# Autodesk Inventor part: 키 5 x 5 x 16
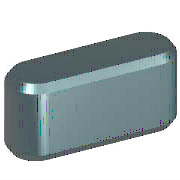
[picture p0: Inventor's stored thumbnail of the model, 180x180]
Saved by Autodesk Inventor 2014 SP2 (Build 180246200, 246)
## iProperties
IsCustomPart: 1
Created: 2012-02
Part Number: 키 5 x 5 x 16
Material: 강철, 연강
Description: 키 및 해당 키홈
Document SubType Name: Modeling
Standard: KS B 1311
Designer: mduedu
Standards Organization: KS
Language: ko-KR
Size Designation: 5 x 5 x 16
Categories: <MemberInstance><Categories><Category DisplayName="샤프트 부품" InternalName="7f7aeb1f-a693-4053-b835-cee3144e0d98" Mnemonic="SHFT"><Category DisplayName="키" Interna
Density: 1 g/cm^3
Appearance: 강철
Author: mduedu
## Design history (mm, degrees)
workplane "Work Plane1"
workplane "Work Plane2"
sketch "스케치1"
  geometry: L1 (2.5, 2.5)-(13.5, 2.5); L2 (13.5, -2.5)-(2.5, -2.5); L3 (0, 9.4)-(0, -7.4) reference; L4 (-5, 0)-(30, 0) reference; L5 (16, 0)-(16, 7); A1 r 2.5 centre (2.5, 0) between (2.5, 2.5) and (2.5, -2.5); A2 r 2.5 centre (13.5, 0) between (13.5, -2.5) and (13.5, 2.5)
  constraints: 6 end point, 5 point on circle, 4 tangent, 3 point on line, 2 centre point, 1 horizontal, 1 parallel, 1 perpendicular
  dimensions: "d0" = 2.5 radius of A1 (= 0.5 x PB); "d13" = 2.5 radius of A2 (= 0.5 x PB); "d14" = 16 distance between parallel lines of L5 L3 (= NLG)
extrude "본체1" new body sketch "스케치1" taper "d3" = 0 deg; stored distance "d4" = 10
workplane "Work Plane3"
body "Solid1"
chamfer "모따기1" distance "d8" = 0.4 (= PHH); stored, may be unused: second distance "d9" = 0.4 (= PHH), angle "d15" = 45 deg
other parameters: "d1" = -3 (= -PNT), "d2" = 2 (= PH - PNT), "NLG" = 16 [user parameter; used in 3 equation terms], "PB" = 5 [user parameter; used in 2 equation terms], "PNT" = 3 [user parameter; used in 2 equation terms], "PH" = 5 [user parameter; used in 1 equation term], "PHH" = 0.4 [user parameter; used in 2 equation terms], "d10" = 0, "d16" = 0, "d17" = 0, "d18" = 0, "WDMIN" = 12 [user parameter], "PLB2" = 16 (= NLG) [user parameter], "WDMAX" = 17 [user parameter], "PLB1" = 16 (= NLG) [user parameter], "RR" = 0.16 [user parameter], "PUEB" = 2.3 [user parameter]
